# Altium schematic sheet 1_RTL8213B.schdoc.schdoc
size 431 x 309 mm; Symbol: Sheet-Symbol_A3; Device: Sheet-Symbol_A3; Company: 嘉立创EDA; Version: V1.0; Page Size: A3; @Project Name: RTL8367S_RTL8213B; @Page Count: 5; @Update Date: 2022-12-07; @Create Date: 2022-10-17; @Schematic Name: Schematic1; @Page No: 1; @Page Name: RTL8213B
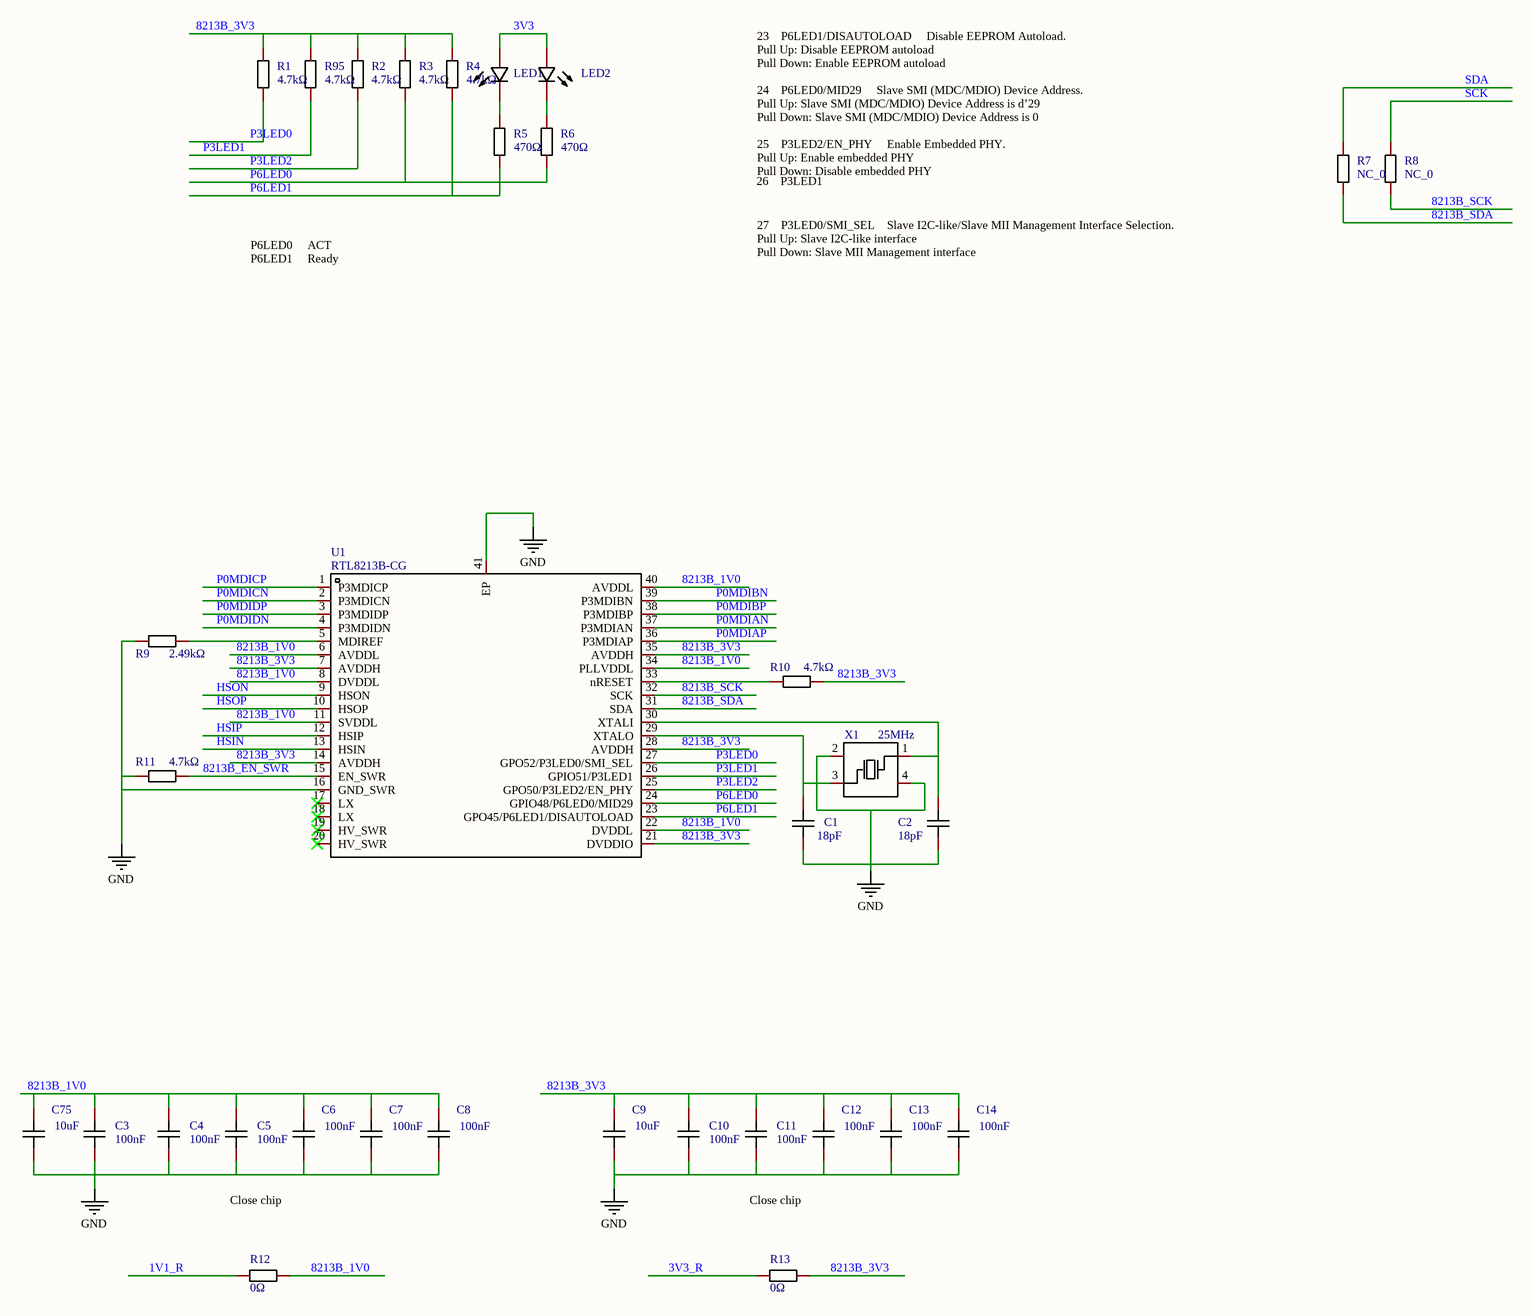
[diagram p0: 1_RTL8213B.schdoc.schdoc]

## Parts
C1  value 18pF  [C0402]  (hidden comment: 0402CG180J500NT)
C2  value 18pF  [C0402]  (hidden comment: 0402CG180J500NT)
C3  value 100nF  [C0402_NEW]  (hidden comment: CL05B104KO5NNNC)
C4  value 100nF  [C0402_NEW]  (hidden comment: CL05B104KO5NNNC)
C5  value 100nF  [C0402_NEW]  (hidden comment: CL05B104KO5NNNC)
C6  value 100nF  [C0402_NEW]  (hidden comment: CL05B104KO5NNNC)
C7  value 100nF  [C0402_NEW]  (hidden comment: CL05B104KO5NNNC)
C8  value 100nF  [C0402_NEW]  (hidden comment: CL05B104KO5NNNC)
C9  value 10uF  [C0603]  (hidden comment: CL10A106MA8NRNC)
C10  value 100nF  [C0402_NEW]  (hidden comment: CL05B104KO5NNNC)
C11  value 100nF  [C0402_NEW]  (hidden comment: CL05B104KO5NNNC)
C12  value 100nF  [C0402_NEW]  (hidden comment: CL05B104KO5NNNC)
C13  value 100nF  [C0402_NEW]  (hidden comment: CL05B104KO5NNNC)
C14  value 100nF  [C0402_NEW]  (hidden comment: CL05B104KO5NNNC)
C75  value 10uF  [C0603]  (hidden comment: CL10A106MA8NRNC)
LED1  19-213/Y2C-CQ2R2L/3T(CY)  [LED0603-R-RD]  (value not drawn)
LED2  19-217/GHC-YR1S2/3T  [LED0603-R-RD]  (value not drawn)
R1  value 4.7kΩ  [R0402]  (hidden comment: 0402WGF4701TCE)
R2  value 4.7kΩ  [R0402]  (hidden comment: 0402WGF4701TCE)
R3  value 4.7kΩ  [R0402]  (hidden comment: 0402WGF4701TCE)
R4  value 4.7kΩ  [R0402]  (hidden comment: 0402WGF4701TCE)
R5  value 470Ω  [R0402]  (hidden comment: 0402WGF4700TCE)
R6  value 470Ω  [R0402]  (hidden comment: 0402WGF4700TCE)
R7  value NC_0  [R0402]  (hidden comment: Res_0402)
R8  value NC_0  [R0402]  (hidden comment: Res_0402)
R9  value 2.49kΩ  [R0402]  (hidden comment: RC0402FR-072K49L)
R10  value 4.7kΩ  [R0402]  (hidden comment: 0402WGF4701TCE)
R11  value 4.7kΩ  [R0402]  (hidden comment: 0402WGF4701TCE)
R12  value 0Ω  [R0603]  (hidden comment: 0603WAF0000T5E)
R13  value 0Ω  [R0603]  (hidden comment: 0603WAF0000T5E)
R95  value 4.7kΩ  [R0402]  (hidden comment: 0402WGF4701TCE)
U1  RTL8213B-CG  [QFN-40_L5.0-W5.0-P0.40-BL-EP3.7]
X1  value 25MHz  [OSC-SMD_4P-L3.2-W2.5-BL]  (hidden comment: X322525MOB4SI)

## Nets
GND: C1.2 C2.1 C3.1 C4.1 C5.1 C6.1 C7.1 C8.1 C9.1 C10.1 C11.1 C12.1 C13.1 C14.1 C75.1 R9.1 R11.1 U1.16(GND_SWR) U1.41(EP) X1.2(GND) X1.4(GND)
1V1_R: R12.1
3V3: LED1.1(A) LED2.1(A)
3V3_R: R13.1
8213B_1V0: C3.2 C4.2 C5.2 C6.2 C7.2 C8.2 C75.2 R12.2 U1.6(AVDDL) U1.8(DVDDL) U1.11(SVDDL) U1.22(DVDDL) U1.34(PLLVDDL) U1.40(AVDDL)
8213B_3V3: C9.2 C10.2 C11.2 C12.2 C13.2 C14.2 R1.2 R2.1 R3.2 R4.2 R10.2 R13.2 R95.2 U1.7(AVDDH) U1.14(AVDDH) U1.21(DVDDIO) U1.28(AVDDH) U1.35(AVDDH)
8213B_EN_SWR: R11.2 U1.15(EN_SWR)
8213B_SCK: R8.1 U1.32(SCK)
8213B_SDA: R7.1 U1.31(SDA)
HSIN: U1.13(HSIN)
HSIP: U1.12(HSIP)
HSON: U1.9(HSON)
HSOP: U1.10(HSOP)
P0MDIAN: U1.37(P3MDIAN)
P0MDIAP: U1.36(P3MDIAP)
P0MDIBN: U1.39(P3MDIBN)
P0MDIBP: U1.38(P3MDIBP)
P0MDICN: U1.2(P3MDICN)
P0MDICP: U1.1(P3MDICP)
P0MDIDN: U1.4(P3MDIDN)
P0MDIDP: U1.3(P3MDIDP)
P3LED0: R1.1 U1.27(GPO52/P3LED0/SMI_SEL)
P3LED1: R95.1 U1.26(GPIO51/P3LED1)
P3LED2: R2.2 U1.25(GPO50/P3LED2/EN_PHY)
P6LED0: R3.1 R6.1 U1.24(GPIO48/P6LED0/MID29)
P6LED1: R4.1 R5.1 U1.23(GPO45/P6LED1/DISAUTOLOAD)
SCK: R8.2
SDA: R7.2
NetC1_1: C1.1 U1.29(XTALO) X1.3(OSC2)
NetC2_2: C2.2 U1.30(XTALI) X1.1(OSC1)
NetLED1_2: LED1.2(K) R5.2
NetLED2_2: LED2.2(K) R6.2
NetR9_2: R9.2 U1.5(MDIREF)
NetR10_1: R10.1 U1.33(nRESET)

Not connected (* = marked no-connect by the designer): U1 17(LX)* 18(LX)* 19(HV_SWR)* 20(HV_SWR)*

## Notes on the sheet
- 23    P6LED1/DISAUTOLOAD     Disable EEPROM Autoload.
  Pull Up: Disable EEPROM autoload
  Pull Down: Enable EEPROM autoload
- 24    P6LED0/MID29     Slave SMI (MDC/MDIO) Device Address.
  Pull Up: Slave SMI (MDC/MDIO) Device Address is d’29
  Pull Down: Slave SMI (MDC/MDIO) Device Address is 0
- 25    P3LED2/EN_PHY     Enable Embedded PHY.
  Pull Up: Enable embedded PHY
  Pull Down: Disable embedded PHY
- 26    P3LED1
- P6LED0     ACT
  P6LED1     Ready
- 27    P3LED0/SMI_SEL    Slave I2C-like/Slave MII Management Interface Selection.
  Pull Up: Slave I2C-like interface
  Pull Down: Slave MII Management interface
- Close chip

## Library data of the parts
C1 C2 = 0402CG180J500NT: Manufacturer: FH(风华); Symbol: C1210X7R475K630NT; Add into BOM: yes; Tolerance: ±5%; Voltage Rated: 50V; Temperature Coefficient: C0G; Description: 容值:18pF;精度:±5%;额定电压:50V;材质(温度系数):C0G;
C3-C8 C10-C14 = CL05B104KO5NNNC: Manufacturer: SAMSUNG(三星); Symbol: C1210X7R475K630NT; Add into BOM: yes; Tolerance: ±10%; Voltage Rated: 16V; Temperature Coefficient: X7R; Description: 容值:100nF;精度:±10%;额定电压:16V;材质(温度系数):X7R;
C9 C75 = CL10A106MA8NRNC: Manufacturer: SAMSUNG(三星); Symbol: C1210X7R475K630NT; Add into BOM: yes; Tolerance: ±20%; Voltage Rated: 25V; Temperature Coefficient: X5R; Description: 容值:10uF;精度:±20%;额定电压:25V;材质(温度系数):X5R;
LED1 = 19-213/Y2C-CQ2R2L/3T(CY): 发光颜色:红灯;; Manufacturer: EVERLIGHT(亿光); Symbol: FC-DA1608HRK-620D; Add into BOM: yes; Illumination Color: 黄色; Luminous Intensity (IF=20mA): 90~180mcd; Dominant Wavelength / Coordinate rank: 585.5~591.5nm; Emitted Color: 红灯
LED2 = 19-217/GHC-YR1S2/3T: 发光颜色:红灯;; Manufacturer: EVERLIGHT(亿光); Symbol: FC-DA1608HRK-620D; Add into BOM: yes; Emitted Color: 翠绿; Lens Color: 无色透明; Dominant Wavelength: 520nm~535nm; Peak Wavelength: 518nm; Forward Current: 20mA; Power Dissipation: 110mW; Viewing Angle: 120°
R1-R4 R10 R11 R95 = 0402WGF4701TCE: Manufacturer: UNI-ROYAL(厚声); Symbol: 电阻; Add into BOM: yes; Tolerance: ±1%; Power(Watts): 1/16W; Temperature Coefficient: ±100ppm/℃; Overload Voltage (Max): 50V; Description: 电阻类型:厚膜电阻;阻值:4.7kΩ;精度:±1%;功率:1/16W;温度系数:±100ppm/℃;最大工作电压:50V;工作温度范围:-55℃~+155℃;
R5 R6 = 0402WGF4700TCE: Manufacturer: UNI-ROYAL(厚声); Symbol: 电阻; Add into BOM: yes; Tolerance: ±1%; Power(Watts): 62.5mW; Temperature Coefficient: ±100ppm/℃; Overload Voltage (Max): 50V; Description: 电阻类型:厚膜电阻;阻值:470Ω;精度:±1%;功率:62.5mW;温度系数:±100ppm/℃;最大工作电压:50V;工作温度范围:-55℃~+155℃;
R7 R8 = Res_0402: Symbol: 电阻; Convert to PCB: yes; Add into BOM: no
R9 = RC0402FR-072K49L: Manufacturer: YAGEO(国巨); Symbol: 电阻; Add into BOM: yes; Power(Watts): 1/16W; Tolerance: ±1%; Temperature Coefficient: ±100ppm/℃; Overload Voltage (Max): 50V; Description: 功率:1/16W;阻值:2.49kΩ;精度:±1%;温度系数:±100ppm/℃;最大工作电压:50V;工作温度范围:-55℃~+155℃;
R12 R13 = 0603WAF0000T5E: Manufacturer: UNI-ROYAL(厚声); Symbol: 电阻; Add into BOM: yes; Tolerance: ±1%; Power(Watts): 1/10W; Overload Voltage (Max): 75V; Description: 温度系数:-;精度:±1%;阻值:0Ω;功率:1/10W;最大工作电压:75V;工作温度范围:-55℃~+155℃;
U1 = RTL8213B-CG: Manufacturer: REALTEK(瑞昱); Add into BOM: yes; Description: 类型:-;标准:-;接口类型:-;电源电压:-;
X1 = X322525MOB4SI: 晶振类型:贴片无源晶振;频率:25MHz;频率公差:±10ppm;频率稳定度:±30ppm;负载电容:16pF;工作温度:-40~+85;; Manufacturer: YXC(扬兴晶振); Symbol: X322525MQB4SI; Add into BOM: yes; Crystal Type: 贴片无源晶振; Frequency Tolerance: ±10ppm; Frequency Stability: ±30ppm; Load Capacitance: 12pF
